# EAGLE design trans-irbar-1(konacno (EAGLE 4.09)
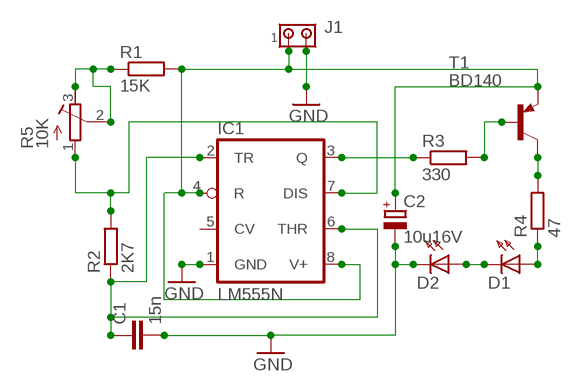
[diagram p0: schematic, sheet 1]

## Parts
C1  15n  C-EU050-024X044  [C050-024X044]
C2  10u16V  CPOL-EUE2.5-5  [E2,5-5]
D1  LEDSFH482  [SFH482]
D2  LEDSFH482  [SFH482]
IC1  LM555N  [DIL08]
J1  MTA02-100  [10X02MTA]
R1  15K  R-EU_0207/10  [0207/10]
R2  2K7  R-EU_0207/10  [0207/10]
R3  330  R-EU_0207/10  [0207/10]
R4  47  R-EU_0207/10  [0207/10]
R5  10K  R-TRIMM64W  [RTRIM64W]
T1  BD140  [TO126]

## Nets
GND: C1.2 C2.- D2.K(C) IC1.1(GND) J1.2
N$1: D1.A R4.1
N$2: C2.+ IC1.4(R) IC1.8(V+) J1.1 R1.2 T1.1(E)
N$3: R4.2 T1.2(C)
N$4: R3.2 T1.3(B)
N$6: D1.K(C) D2.A
N$7: IC1.7(DIS) R2.2 R5.1(E)
N$8: C1.1 IC1.2(TR) IC1.6(THR) R2.1
N$9: R1.1 R5.2(S) R5.3(A)
N$11: IC1.3(Q) R3.1
Unconnected: IC1.5(CV)

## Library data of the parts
C1 = rcl:C-EU: CAPACITOR, European symbol
C2 = rcl:CPOL-EU: POLARIZED CAPACITOR, European symbol
D1 D2 = led:LED: LED
IC1 = linear:*555: TIMER
J1 = con-amp:MTA02-100: AMP connector
R1-R4 = rcl:R-EU_: RESISTOR, European symbol
R5 = rcl:R-TRIMM: Trimm resistor
T1 = transistor-pnp:BD140: PNP Transistor

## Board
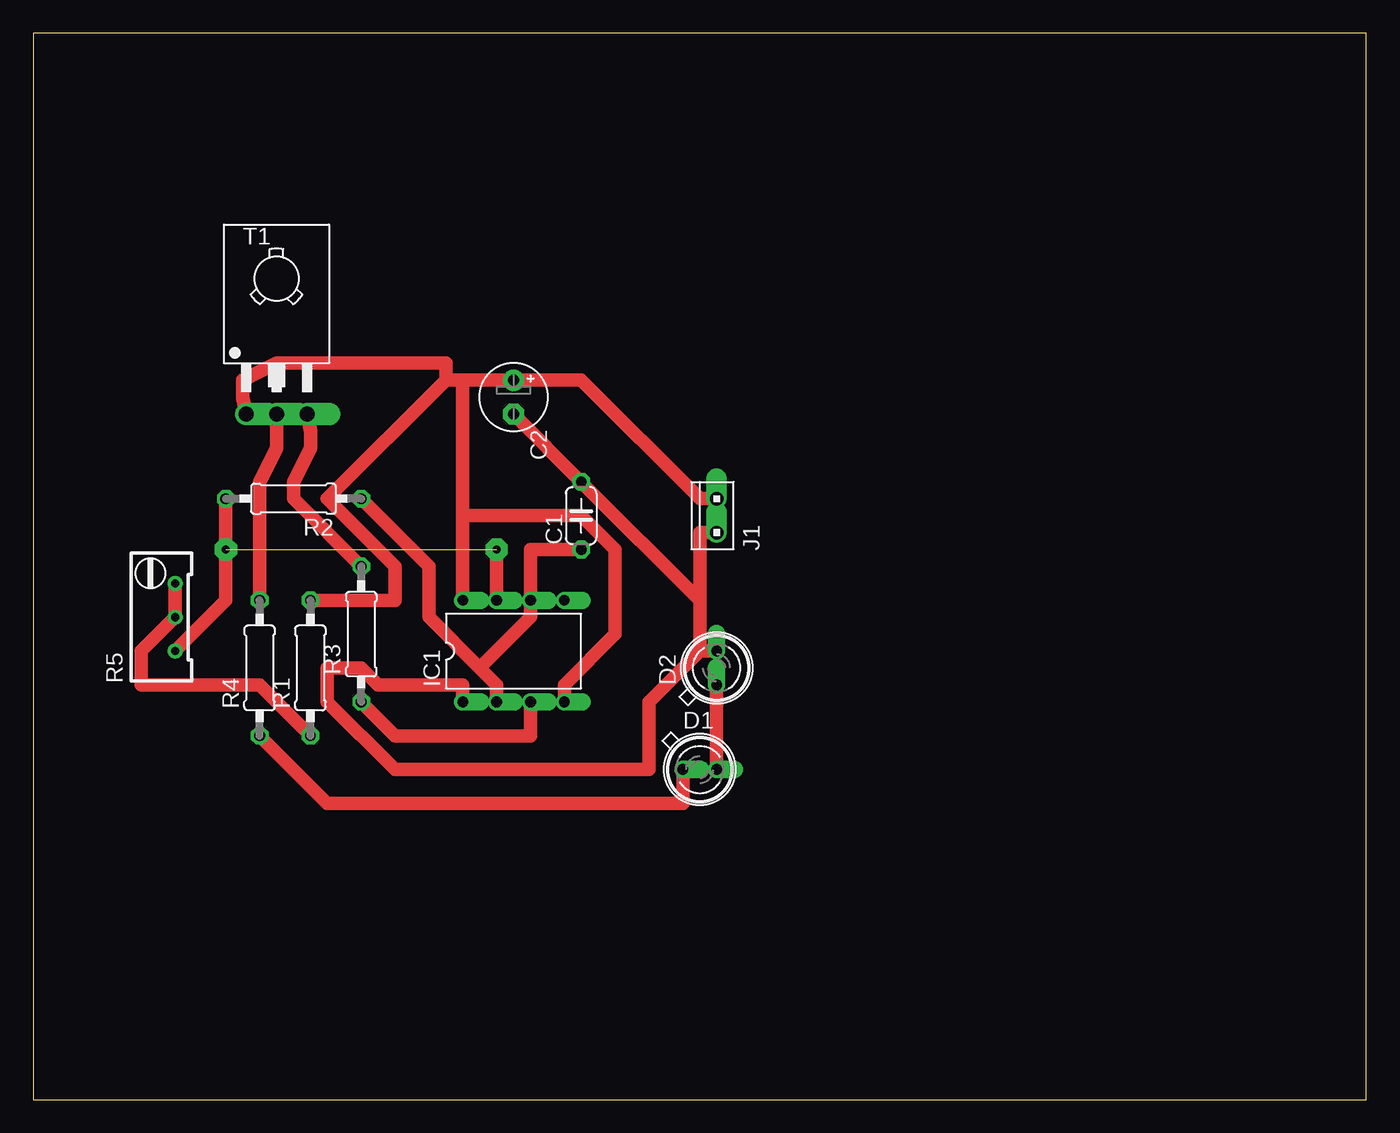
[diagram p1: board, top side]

Size 100 x 80 mm. Coordinates in mm from the lower left corner, seen from the top.
Outline: 0,0 100,0 100,80 0,80 0,0
Copper layers used: Top

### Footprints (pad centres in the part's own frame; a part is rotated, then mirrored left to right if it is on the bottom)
C050-024X044 = drill 0.813 octagon: 1 -2.54,0; 2 2.54,0
E2,5-5 = drill 0.813 pad 1.6 round: + -1.27,0 | drill 0.813 pad 1.6 octagon: - 1.27,0
SFH482 = drill 0.813 offset: A -1.27,0; K 1.27,0
DIL08 = drill 0.813 offset: 1 -3.81,-3.81; 2 -1.27,-3.81; 3 1.27,-3.81; 4 3.81,-3.81; 5 3.81,3.81; 6 1.27,3.81; 7 -1.27,3.81; 8 -3.81,3.81
10X02MTA = drill 1.016 offset: 1 1.27,0; 2 -1.27,0
0207/10 = drill 0.813 octagon: 1 -5.08,0; 2 5.08,0
RTRIM64W = drill 0.61 round: 1 1.27,-2.54; 2 1.27,0; 3 1.27,2.54
TO126 = drill 1.118 offset: 1 -2.286,-5.08; 2 0,-5.08; 3 2.286,-5.08 | hole 3.302: 0,5.08

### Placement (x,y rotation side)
C1  41.11,43.81 90 top
C2  36.03,52.7 270 top
D1  50,24.76 0 top
D2  51.27,32.38 90 top
IC1  36.03,33.65 0 top
J1  51.27,43.81 90 top
R1  20.79,32.38 90 top
R2  19.52,45.08 180 top
R3  24.6,34.92 90 top
R4  16.98,32.38 90 top
R5  9.36,36.19 0 top
T1  18.25,56.51 0 top

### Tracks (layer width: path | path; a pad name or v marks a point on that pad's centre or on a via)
GND
  Top 1.016: C2.- C1.2 50,37.46 | 50,33.65 46.19,29.84 46.19,24.76 27.14,24.76 22.06,29.84 22.06,32.38 24.6,32.38 25.87,31.11 32.22,31.11 IC1.1 | 50,33.65 50,37.46 | 50,37.46 50,42.54 J1.2 | 50,33.65 D2.K
N$1
  Top 1.016: R4.1 22.06,22.22 48.73,22.22 D1.A
N$2
  Top 1.016: R1.2 27.14,37.46 27.14,40 22.06,45.08 30.95,53.97 | 32.22,53.97 C2.+ 41.11,53.97 50,45.08 J1.1 | 30.95,53.97 32.22,53.97 | 32.22,53.97 32.22,43.81 | 32.22,43.81 IC1.8 | 32.22,43.81 41.11,43.81 43.65,41.27 43.65,34.92 39.84,31.11 IC1.4 | 30.95,53.97 30.95,55.24 18.25,55.24 15.71,53.97 15.71,52.7 T1.1
N$3
  Top 1.016: R4.2 16.98,46.35 18.25,48.89 T1.2
N$4
  Top 1.016: R3.2 19.52,45.08 19.52,46.35 20.79,48.89 20.79,50.16 T1.3
N$5  (via drill 0.61 pad 1.68)
  other vias: 34.76,41.27
N$6
  Top 1.016: D1.K D2.A
N$7  (via drill 0.61 pad 1.68)  (1 unrouted)
  Top 1.016: R5.1 14.44,37.46 v14.44,41.27 R2.2 | IC1.7 34.76,41.27
N$8
  Top 1.016: R2.1 29.68,40 29.68,36.19 33.49,32.38 | 33.49,32.38 34.76,31.11 IC1.2 | 33.49,32.38 37.3,36.19 IC1.6 37.3,41.27 C1.1
N$9
  Top 1.016: R5.3 R5.2 8.09,33.65 8.09,31.11 16.98,31.11 R1.1
N$11
  Top 1.016: R3.1 27.14,27.3 37.3,27.3 IC1.3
